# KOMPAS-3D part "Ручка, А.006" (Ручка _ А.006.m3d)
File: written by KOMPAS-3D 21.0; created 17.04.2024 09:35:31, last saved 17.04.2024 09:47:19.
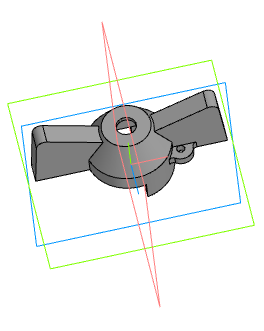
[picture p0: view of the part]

Document properties: Автор: Admin; Полное имя файла: C:\Users\wsr\Desktop\Чертежи\Детали\Ручка _ А.006.m3d

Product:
- Part/product: Ручка  | designation А.006
    Масса: 0.02807

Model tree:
1. Эскиз:1
2. Элемент выдавливания:1
     Расстояние 1 = 9
3. Смещенная плоскость:1  (with: Элемент выдавливания:1)
     Расстояние = 7
4. Эскиз:2  (with: Элемент выдавливания:1)
5. Элемент по сечениям:1  (with: Элемент выдавливания:1)
6. Эскиз:3  (with: Элемент выдавливания:1)
7. Элемент выдавливания:2
     Расстояние 2 = 8.5
8. Эскиз:4  (with: Элемент выдавливания:2, Элемент по сечениям:1)
9. Элемент вращения:1
     Угол 1 = 360
10. Эскиз:5  (with: Элемент вращения:1)
11. Элемент выдавливания:3
     Расстояние 2 = 4
12. Эскиз:6  (with: Элемент выдавливания:3)
13. Элемент выдавливания:4
     Расстояние 2 = 8
14. Эскиз:7  (with: Элемент по сечениям:1)
15. Элемент выдавливания:5
     Расстояние 1 = 5
16. Удалить грани:1  (with: Элемент выдавливания:5)
17. Удалить грани:2  (with: Элемент выдавливания:5)
18. Эскиз:8  (with: Элемент выдавливания:1, Элемент выдавливания:2)
19. Элемент выдавливания:6  (with: Элемент выдавливания:5)
     Расстояние 2 = 5
20. Эскиз:9  (with: Элемент выдавливания:5)
21. Элемент выдавливания:7
     Расстояние 2 = 2
22. Зеркальный массив:1
23. Экземпляр ( 1 )
24. Экземпляр ( 2 )  (with: Элемент выдавливания:7)
25. Зеркальный массив:2  (with: Экземпляр ( 1 ), Экземпляр ( 2 ), Элемент выдавливания:5)
26. Удалить грани:3  (with: Элемент выдавливания:5)
27. Удалить грани:4  (with: Элемент выдавливания:5)
28. Скругление:1  (with: Элемент выдавливания:7)
     Радиус = 1

Expressions: 47/2
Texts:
  Точка начала. Х
  Точка начала. Y
  Точка начала. Z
